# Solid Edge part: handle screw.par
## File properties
Title: Handle Screw
Author: Deepak Maini
Template: Normal.par
Last saved by: Robert a Rhodes jr
Revision: 6
Application: Solid Edge
Material: aluminum
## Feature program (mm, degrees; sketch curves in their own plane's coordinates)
sketch for "unnamed Protrusion 1" plane through (0, 0, 0) normal (0, -1, 0) x-axis (1, 0, 0)
  circle centre (0, 0) radius 7.5
extrude "unnamed Protrusion 1" add finite 14 along +normal
sketch for "unnamed Hole 1" plane through (0, -14, 0) normal (0, -1, 0) x-axis (1, 0, 0)
  hole centre (0, 0) bore radius 4
hole "unnamed Hole 1" finite
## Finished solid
Body 1: solid body, 5 faces, 4 edges, 1 vertex.
  Faces by surface: cylinder 2, plane 2, cone 1
  Edges by curve: circle 4
Bounding box of the edges (mm): 15.000 x 14.000 x 15.000, from (-7.5, -14, -7.5) to (7.5, 0, 7.5).
Cylindrical faces by radius (mm): R4 x1, R7.5 x1
Conical faces (half-angle, radius in mm at the cone's reference point): 59 deg R4 x1
Planar faces by outward normal: +y 1, -y 1
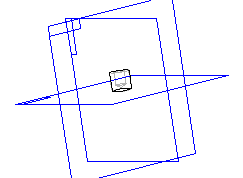
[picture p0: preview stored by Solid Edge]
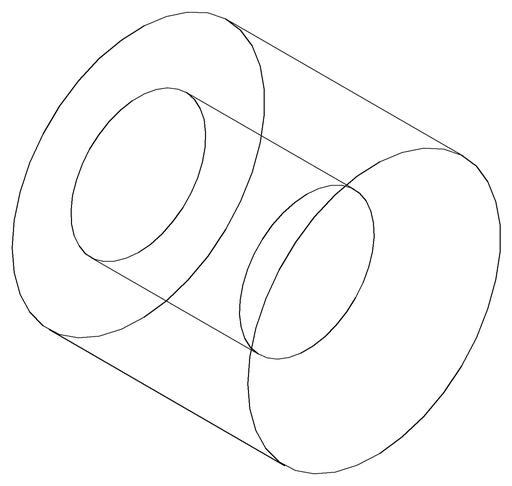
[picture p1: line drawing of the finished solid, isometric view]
